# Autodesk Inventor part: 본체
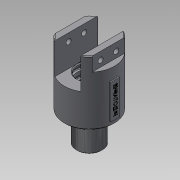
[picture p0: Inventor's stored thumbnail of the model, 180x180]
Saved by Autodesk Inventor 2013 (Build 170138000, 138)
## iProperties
Created: 2019-02
Part Number: 본체
Material: 일반
Document SubType Name: Modeling
Designer: Administrator
Density: 1 g/cm^3
Author: Administrator
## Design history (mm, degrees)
sketch "스케치1"
  geometry: C1 r 29 at (0, 0); 1 further point
  constraints: 1 centre point, 1 coincident
  dimensions: "d0" = 58 diameter of C1
extrude "돌출1" new body sketch "스케치1" distance "d2" = 74; taper "d3" = 0 deg
sketch "스케치2"
  geometry: L1 (0, 0)-(15, 0); L2 (0, 0)-(-15, 0); L3 (-15, 0)-(-15, 24.819); L4 (-15, 0)-(-15, -24.819); L5 (15, 0)-(15, 24.819); L6 (15, 0)-(15, -24.819); A1 r 29 centre (0, 0) between (-15, 24.819) and (-15, -24.819) reference
  constraints: 12 end point, 4 equal length, 4 point on circle, 1 horizontal, 1 perpendicular
  dimensions: "d4" = 15 distance of L1.start L1.end; "d5" = 15 distance of L1.start L2.end
extrude "돌출2" cut sketch "스케치2" distance "d6" = 36; taper "d7" = 0 deg
sketch "스케치3"
  geometry: L1 (15, 24.819)-(15, -24.819) reference; L2 (0, 0)-(-22, 0); L3 (0, 0)-(22, 0); L4 (-22, 0)-(-22, 18.894); L5 (-22, 0)-(-22, -18.894); L6 (22, 0)-(22, 18.894); L7 (22, 0)-(22, -18.894); A1 r 29 centre (0, 0) between (-15, 24.819) and (-15, -24.819) reference; A2 r 29 centre (0, 0) between (15, -24.819) and (15, 24.819) reference
  constraints: 12 end point, 4 equal length, 4 point on circle, 2 perpendicular
  dimensions: "d8" = 22 distance of L2.start L2.end; "d9" = 22 distance of L2.start L3.end
extrude "돌출3" cut sketch "스케치3" distance "d10" = 16; taper "d11" = 0 deg
sketch "스케치4"
  geometry: L1 (0, 0)-(0, 37.789) reference; L2 (0, 37.789)-(16, 37.789) reference; L3 (0, 18.894)-(9, 18.894); L4 (9, 18.894)-(9, 27.894); L5 (9, 18.894)-(9, 9.894); C1 r 3 at (9, 27.894); C2 r 3 at (9, 9.894); 1 further point
  constraints: 6 end point, 2 centre point, 2 coincident, 1 collinear, 1 midpoint, 1 parallel, 1 perpendicular
  dimensions: "d12" = 9 distance of L3.start L3.end; "d14" = 9 distance of L3.end L4.end; "d15" = 9 distance of L3.end L5.end; "d16" = 6 diameter of C1; "d17" = 6 diameter of C2
extrude "돌출4" cut sketch "스케치4" stored distance "d18" = 16; taper "d19" = 0 deg
sketch "스케치5"
  geometry: C1 r 29 at (0, 0) reference; C2 r 13 at (0, 0)
  constraints: 1 centre point, 1 coincident
  dimensions: "d20" = 26 diameter of C2
extrude "돌출5" join sketch "스케치5" distance "d21" = 5; taper "d22" = 0 deg
sketch "스케치6"
  geometry: C1 r 13 at (0, 0) reference; C2 r 15 at (0, 0)
  constraints: 1 centre point, 1 coincident
  dimensions: "d23" = 30 diameter of C2
extrude "돌출6" join sketch "스케치6" distance "d24" = 29; taper "d25" = 0 deg
feature "스레드1" dims "d26" = 10, "d27" = 0
chamfer "모따기1" distance "d28" = 1; stored, may be unused: second distance "d29" = 2, angle "d30" = 45 deg
sketch "스케치7"
  geometry: C1 r 14 at (0, 0) reference
hole "구멍1" sketch "스케치7" at (0, 0) diameter "d31" = 12.376; stored, may be unused: countersink angle "d35" = 90 deg, drill point angle "d37" = 118 deg; dims "d32" = 18, "d33" = 4, "d34" = 2, "d36" = 22
node "작업 평면1"
sketch "스케치8"
  geometry: L1 (-24.819, 38)-(24.819, 38) reference; L2 (0, 38)-(0, 11); L3 (0, 38)-(14, 38); L4 (14, 38)-(14, 18); L5 (14, 18)-(16, 18); L6 (16, 18)-(16, 11); L7 (16, 11)-(0, 11); L8 (14, 38)-(14, 33); L9 (0, 33)-(17, 33); L10 (17, 33)-(17, 35.35); L11 (17, 33)-(17, 30.65); L12 (0, 33)-(0, 24); L13 (0, 24)-(17, 24); L14 (17, 24)-(17, 26.35); L15 (17, 24)-(17, 21.65); L16 (17, 30.65)-(14, 30.65); L17 (17, 26.35)-(14, 26.35); L18 (17, 21.65)-(14, 21.65); L19 (17, 35.35)-(14, 35.35); 2 further points
  constraints: 36 end point, 10 perpendicular, 8 point on line, 3 parallel, 2 collinear, 2 midpoint
  dimensions: "d63" = 27 distance of L2.start L2.end; "d64" = 32 diameter of L6 L2; "d65" = 28 diameter of L4 L2; "d66" = 5 distance of L3.end L8.end; "d67" = 34 diameter of L9.end L2; "d68" = 7 distance of L5.end L6.end; "d69" = 2.35 distance of L9.end L10.end; "d70" = 2.35 distance of L9.end L11.end; "d71" = 9 distance of L9.start L12.end; "d72" = 34 diameter of L13.end L2; "d73" = 2.35 distance of L13.end L14.end; "d74" = 2.35 distance of L13.end L15.end
revolve "회전1" sketch "스케치8" stored, may be unused: angle "d75" = 90 deg
chamfer "모따기2" distance "d76" = 1; stored, may be unused: second distance "d77" = 2, angle "d78" = 45 deg
fillet "모깎기1" dims "d79" = 0.8
sketch "스케치10"
  geometry: C1 r 14 at (0, 0) reference; C2 r 4 at (0, 0)
  constraints: 1 centre point, 1 coincident
  dimensions: "d80" = 8 diameter of C2
extrude "돌출7" cut sketch "스케치10" stored distance "d81" = 29; taper "d82" = 0 deg
node "작업 평면3"
sketch "스케치12"
  geometry: L1 (0, 0)-(0, 5); L2 (0, 5)-(5, 5); L3 (5, 5)-(5, 45); L4 (5, 45)-(0, 45); L5 (0, 45)-(0, 5); L6 (-5, 5)-(-5, 45); L7 (-5, 45)-(0, 45); L8 (0, 5)-(-5, 5)
  constraints: 16 end point, 2 parallel, 2 symmetric about line, 1 horizontal, 1 perpendicular, 1 vertical
  dimensions: "d89" = 5 distance of L1.start L1.end; "d90" = 5 distance of L4.end L3.end; "d91" = 40 distance of L3.end L2.end
extrude "돌출8" join sketch "스케치12" stored distance "d92" = 29; taper "d93" = 0 deg
node "작업 평면4"
sketch "스케치13"
  geometry: L1 (5, 45)-(-5, 45) reference; L2 (-5, 45)-(-5, 5) reference; 2 further points
  constraints: 1 other
  dimensions: "d95" = 20 distance from line of point (0, 25) L1; "d96" = 5 distance from line of L2 point (0, 25)
feature "엠보싱1" sketch "스케치13" dims "d8" = 22, "d97" = 0.5, "d98" = 0
chamfer "모따기4" distance "d99" = 1; stored, may be unused: second distance "d100" = 2, angle "d101" = 45 deg
chamfer "모따기5" distance "d102" = 1; stored, may be unused: second distance "d103" = 2, angle "d104" = 45 deg
node "솔리드1"
node "투영된 루프1"
other parameters: "d38" = 0, "d94" = 42
